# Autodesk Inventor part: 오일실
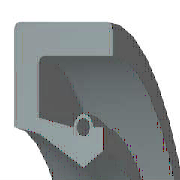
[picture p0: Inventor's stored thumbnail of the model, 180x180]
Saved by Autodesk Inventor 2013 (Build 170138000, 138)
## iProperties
IsCustomPart: 0
Company: 한국ATC센터
Created: 2014-08
Part Number: 오일실
Material: 고무
Description: 오일-실
Document SubType Name: Modeling
Standard: KS B 2804
Designer: KYOUNG IL JANG
Standards Organization: KS
Language: ko-KR
Size Designation: S - 17 30 8
Categories: <MemberInstance><Categories><Category DisplayName="샤프트 부품" InternalName="7f7aeb1f-a693-4053-b835-cee3144e0d98" Mnemonic="SHFT"><Category DisplayName="실링" Intern
Density: 0.93 g/cm^3
Author: KYOUNG IL JANG
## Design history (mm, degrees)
revolve "본체" stored, may be unused: angle "d17" = 90 deg
revolve "스프링1" stored, may be unused: angle "d18" = 90 deg
body "Solid1"
sketch "스케치1"
  geometry: L1 (0, 15)-(8, 15); L2 (8, 15)-(8, 13.75); L3 (8, 13.75)-(1.75, 13.75); L4 (0, 15)-(0, 10.6); L5 (0, 10.6)-(1.75, 10.25); L6 (1.75, 10.25)-(4.9, 8.5); L7 (4.9, 8.5)-(0, 8.5); L8 (6.3, 9.375)-(6.3, 10.6); L9 (0, 0)-(9.586, 0) reference; L10 (4.9, 8.5)-(6.3, 9.375); L11 (0, 18)-(0, -3) reference; L12 (-1.917, 0)-(11.503, 0) reference; L13 (4.2, 10.6)-(1.75, 11.09); L14 (1.75, 11.09)-(1.75, 13.75); L15 (6.3, 10.6)-(5.6, 10.6); C1 r 0.455 at (4.9, 10.6); A1 r 0.7 centre (4.9, 10.6) between (5.6, 10.6) and (4.2, 10.6)
  constraints: 26 end point, 5 horizontal alignment, 4 perpendicular, 2 centre point, 2 collinear, 2 horizontal, 2 parallel, 2 point on circle, 2 point on line, 2 vertical alignment, 1 coincident
  dimensions: "d0" = 30 diameter of L1 L9 (= SD2); "d1" = 18.75 diameter of L8.start L9 (= ABDM); "d2" = 1.25 distance of L1.end L2.end (computed from SD); "d3" = 0.91 diameter of C1 (= SPDI); "d4" = 1.4 diameter of A1 (= SPDA); "d5" = 17 diameter of L6.end L9 (= NND); "d6" = 20.5 diameter of L5.end L9 (= TKDM); "d7" = 21.2 diameter of L4.end L9 (= HLDM); "d8" = 4.9 distance from line of C1.centre L4 (= SPDST); "d9" = 6.3 distance between parallel lines of L8 L4 (= SDI); "d10" = 8 distance between parallel lines of L2 L4 (= SWDT); "d12" = 1.75 distance between parallel lines of L14 L4 (= SD)
fillet "모깎기1" dims "d11" = 0.3 (= RR)
other parameters: "SD2" = 30 [user parameter; used in 1 equation term], "SWDT" = 8 [user parameter; used in 1 equation term], "RR" = 0.3 [user parameter; used in 1 equation term], "SD" = 1.75 [user parameter; used in 2 equation terms], "NND" = 17 [user parameter; used in 1 equation term], "SPDA" = 1.4 [user parameter; used in 1 equation term], "SPDI" = 0.91 [user parameter; used in 1 equation term], "TKDM" = 20.5 [user parameter; used in 1 equation term], "HLDM" = 21.2 [user parameter; used in 1 equation term], "ABDM" = 18.75 [user parameter; used in 1 equation term], "SDI" = 6.3 [user parameter; used in 1 equation term], "SPDST" = 4.9 [user parameter; used in 1 equation term], "d13" = 0, "d14" = 0, "d15" = 0, "LAB" = 0.35 [user parameter]
